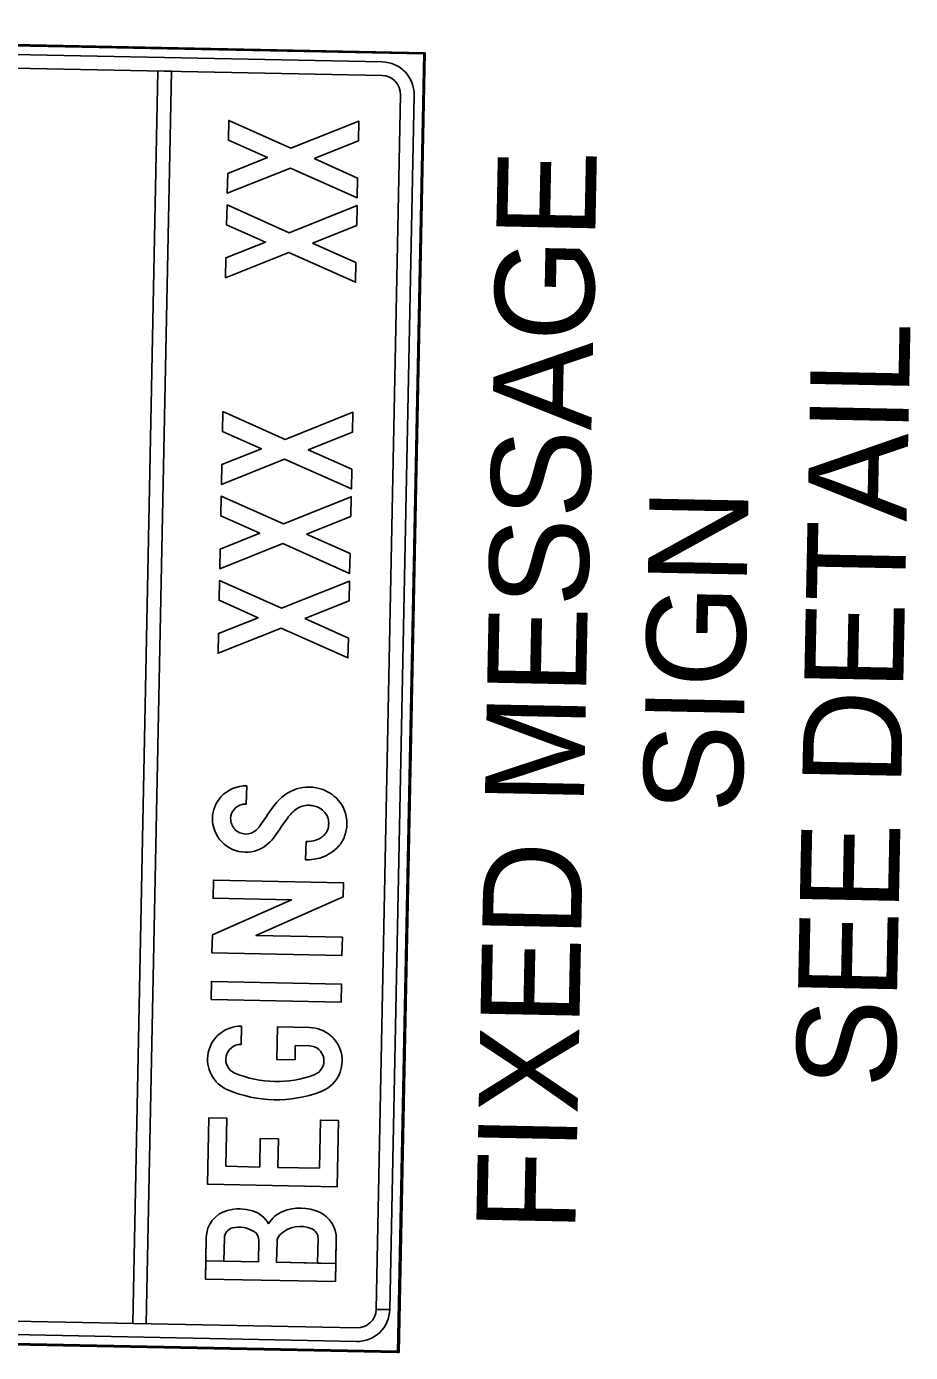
# Model space of a CAD drawing. Extents: x 331323 to 388339, y 121519 to 205315.
# Drawn here: x 366237 to 366773, y 139118 to 139921 of the extents above; entities that cross this region are included whole.
import ezdxf

# ---------------------------------------------------------------- set-up
doc = ezdxf.new("R2010")
doc.units = 0
doc.layers.add('P_MISC_TXT', color=7, linetype='Continuous')
doc.layers.add('P_SGN_Cell', color=7, linetype='Continuous')

msp = doc.modelspace()

# ---------------------------------------------------------------- linework, layer by layer
at = {"layer": 'P_MISC_TXT'}
for p, q in [((366478.7, 139904.99), (365691.28, 139920.84)), ((366478.7, 139904.99), (365691.28, 139920.84)), ((365692.08, 139920), (366477.86, 139904.19)), ((366452.74, 139899.36), (365716.99, 139914.17)), ((365716.82, 139905.96), (366452.58, 139891.16)), ((366462.86, 139117.57), (366478.7, 139904.99)), ((366462.86, 139117.57), (366478.7, 139904.99)), ((366477.86, 139904.19), (366462.03, 139117.59)), ((366316.85, 139893.89), (366301.58, 139135.17)), ((366316.85, 139893.89), (366301.58, 139135.17)), ((366316.85, 139893.89), (366301.58, 139135.17)), ((366309.79, 139135.01), (366325.05, 139893.73)), ((366309.79, 139135.01), (366325.05, 139893.73)), ((366309.79, 139135.01), (366325.05, 139893.73)), ((366325.05, 139893.73), (366316.85, 139893.89)), ((366325.05, 139893.73), (366316.85, 139893.89)), ((366325.05, 139893.73), (366316.85, 139893.89)), ((366463.83, 139879.45), (366449.03, 139143.77)), ((366457.23, 139143.61), (366472.03, 139879.28)), ((366367.18, 139304.19), (366367.4, 139315.21)), ((366367.18, 139304.19), (366367.4, 139315.21)), ((366367.18, 139304.19), (366367.4, 139315.21)), ((366400.05, 139303.52), (366408.51, 139303.35)), ((366400.05, 139303.52), (366408.51, 139303.35)), ((366400.05, 139303.52), (366408.51, 139303.35)), ((366437.31, 139132.44), (365701.56, 139147.25)), ((366457.22, 139143.53), (366449.02, 139143.69)), ((366449.03, 139143.77), (366457.23, 139143.61)), ((365675.44, 139133.42), (366462.86, 139117.57)), ((365675.44, 139133.42), (366462.03, 139117.59)), ((366462.04, 139118.41), (365676.27, 139134.22)), ((365701.39, 139139.05), (366437.15, 139124.24)), ((366301.58, 139135.17), (366309.79, 139135.01)), ((366301.58, 139135.17), (366309.79, 139135.01)), ((366301.58, 139135.17), (366309.79, 139135.01)), ((366462.03, 139117.59), (366462.04, 139118.41)), ((366462.03, 139117.59), (366462.86, 139117.57))]:
    msp.add_line(p, q, dxfattribs=at)
for points in [[(366411.41, 139840.82), (366438.25, 139851.54), (366438.49, 139863.51), (366397.38, 139847.09), (366359.74, 139863.91), (366359.5, 139851.94), (366383.11, 139841.39), (366359.09, 139831.79), (366358.85, 139819.82), (366397.14, 139835.12), (366437.55, 139817.06), (366437.79, 139829.03)], [(366411.41, 139840.82), (366438.25, 139851.54), (366438.49, 139863.51), (366397.38, 139847.09), (366359.74, 139863.91), (366359.5, 139851.94), (366383.11, 139841.39), (366359.09, 139831.79), (366358.85, 139819.82), (366397.14, 139835.12), (366437.55, 139817.06), (366437.79, 139829.03)], [(366411.41, 139840.82), (366438.25, 139851.54), (366438.49, 139863.51), (366397.38, 139847.09), (366359.74, 139863.91), (366359.5, 139851.94), (366383.11, 139841.39), (366359.09, 139831.79), (366358.85, 139819.82), (366397.14, 139835.12), (366437.55, 139817.06), (366437.79, 139829.03)], [(366410.38, 139789.65), (366437.22, 139800.37), (366437.46, 139812.34), (366396.35, 139795.92), (366358.71, 139812.74), (366358.47, 139800.77), (366382.08, 139790.22), (366358.06, 139780.62), (366357.82, 139768.65), (366396.11, 139783.95), (366436.52, 139765.89), (366436.76, 139777.85)], [(366410.38, 139789.65), (366437.22, 139800.37), (366437.46, 139812.34), (366396.35, 139795.92), (366358.71, 139812.74), (366358.47, 139800.77), (366382.08, 139790.22), (366358.06, 139780.62), (366357.82, 139768.65), (366396.11, 139783.95), (366436.52, 139765.89), (366436.76, 139777.85)], [(366410.38, 139789.65), (366437.22, 139800.37), (366437.46, 139812.34), (366396.35, 139795.92), (366358.71, 139812.74), (366358.47, 139800.77), (366382.08, 139790.22), (366358.06, 139780.62), (366357.82, 139768.65), (366396.11, 139783.95), (366436.52, 139765.89), (366436.76, 139777.85)], [(366407.86, 139664.47), (366434.7, 139675.19), (366434.94, 139687.16), (366393.83, 139670.74), (366356.19, 139687.56), (366355.95, 139675.6), (366379.57, 139665.04), (366355.54, 139655.45), (366355.3, 139643.48), (366393.59, 139658.77), (366434, 139640.71), (366434.24, 139652.68)], [(366407.86, 139664.47), (366434.7, 139675.19), (366434.94, 139687.16), (366393.83, 139670.74), (366356.19, 139687.56), (366355.95, 139675.6), (366379.57, 139665.04), (366355.54, 139655.45), (366355.3, 139643.48), (366393.59, 139658.77), (366434, 139640.71), (366434.24, 139652.68)], [(366407.86, 139664.47), (366434.7, 139675.19), (366434.94, 139687.16), (366393.83, 139670.74), (366356.19, 139687.56), (366355.95, 139675.6), (366379.57, 139665.04), (366355.54, 139655.45), (366355.3, 139643.48), (366393.59, 139658.77), (366434, 139640.71), (366434.24, 139652.68)], [(366406.83, 139613.3), (366433.67, 139624.02), (366433.91, 139635.99), (366392.8, 139619.57), (366355.16, 139636.39), (366354.92, 139624.43), (366378.54, 139613.87), (366354.51, 139604.27), (366354.27, 139592.31), (366392.56, 139607.6), (366432.97, 139589.54), (366433.21, 139601.51)], [(366406.83, 139613.3), (366433.67, 139624.02), (366433.91, 139635.99), (366392.8, 139619.57), (366355.16, 139636.39), (366354.92, 139624.43), (366378.54, 139613.87), (366354.51, 139604.27), (366354.27, 139592.31), (366392.56, 139607.6), (366432.97, 139589.54), (366433.21, 139601.51)], [(366406.83, 139613.3), (366433.67, 139624.02), (366433.91, 139635.99), (366392.8, 139619.57), (366355.16, 139636.39), (366354.92, 139624.43), (366378.54, 139613.87), (366354.51, 139604.27), (366354.27, 139592.31), (366392.56, 139607.6), (366432.97, 139589.54), (366433.21, 139601.51)], [(366405.8, 139562.13), (366432.64, 139572.85), (366432.88, 139584.82), (366391.77, 139568.4), (366354.13, 139585.22), (366353.89, 139573.25), (366377.51, 139562.7), (366353.48, 139553.1), (366353.24, 139541.13), (366391.53, 139556.43), (366431.94, 139538.37), (366432.18, 139550.34)], [(366405.8, 139562.13), (366432.64, 139572.85), (366432.88, 139584.82), (366391.77, 139568.4), (366354.13, 139585.22), (366353.89, 139573.25), (366377.51, 139562.7), (366353.48, 139553.1), (366353.24, 139541.13), (366391.53, 139556.43), (366431.94, 139538.37), (366432.18, 139550.34)], [(366405.8, 139562.13), (366432.64, 139572.85), (366432.88, 139584.82), (366391.77, 139568.4), (366354.13, 139585.22), (366353.89, 139573.25), (366377.51, 139562.7), (366353.48, 139553.1), (366353.24, 139541.13), (366391.53, 139556.43), (366431.94, 139538.37), (366432.18, 139550.34)], [(366429.03, 139393.51), (366429.2, 139402.17), (366350.48, 139403.76), (366350.26, 139392.74), (366397.83, 139391.78), (366349.81, 139370.56), (366349.59, 139359.67), (366428.32, 139358.09), (366428.54, 139369.11), (366376.18, 139370.16)], [(366429.03, 139393.51), (366429.2, 139402.17), (366350.48, 139403.76), (366350.26, 139392.74), (366397.83, 139391.78), (366349.81, 139370.56), (366349.59, 139359.67), (366428.32, 139358.09), (366428.54, 139369.11), (366376.18, 139370.16)], [(366429.03, 139393.51), (366429.2, 139402.17), (366350.48, 139403.76), (366350.26, 139392.74), (366397.83, 139391.78), (366349.81, 139370.56), (366349.59, 139359.67), (366428.32, 139358.09), (366428.54, 139369.11), (366376.18, 139370.16)], [(366349.02, 139331.33), (366349.24, 139342.35), (366427.97, 139340.77), (366427.75, 139329.75)], [(366349.02, 139331.33), (366349.24, 139342.35), (366427.97, 139340.77), (366427.75, 139329.75)], [(366349.02, 139331.33), (366349.24, 139342.35), (366427.97, 139340.77), (366427.75, 139329.75)], [(366414.7, 139229.2), (366389.5, 139229.7), (366389.85, 139246.95), (366378.83, 139247.17), (366378.48, 139229.93), (366358.01, 139230.34), (366358.6, 139259.47), (366347.58, 139259.69), (366346.77, 139219.54), (366425.5, 139217.95), (366426.3, 139258.1), (366415.28, 139258.33)], [(366414.7, 139229.2), (366389.5, 139229.7), (366389.85, 139246.95), (366378.83, 139247.17), (366378.48, 139229.93), (366358.01, 139230.34), (366358.6, 139259.47), (366347.58, 139259.69), (366346.77, 139219.54), (366425.5, 139217.95), (366426.3, 139258.1), (366415.28, 139258.33)], [(366414.7, 139229.2), (366389.5, 139229.7), (366389.85, 139246.95), (366378.83, 139247.17), (366378.48, 139229.93), (366358.01, 139230.34), (366358.6, 139259.47), (366347.58, 139259.69), (366346.77, 139219.54), (366425.5, 139217.95), (366426.3, 139258.1), (366415.28, 139258.33)]]:
    msp.add_lwpolyline(points, close=True, dxfattribs=at)
for points in [[(366370.37, 139449.82), (366370.59, 139460.85)], [(366370.37, 139449.82), (366370.59, 139460.85)], [(366370.37, 139449.82), (366370.59, 139460.85)], [(366406.53, 139427.04), (366406.3, 139416.02)], [(366406.53, 139427.04), (366406.3, 139416.02)], [(366406.53, 139427.04), (366406.3, 139416.02)], [(366408.73, 139314.38), (366389.25, 139314.77), (366388.85, 139295.09), (366399.87, 139294.86), (366400.05, 139303.52)], [(366408.73, 139314.38), (366389.25, 139314.77), (366388.85, 139295.09), (366399.87, 139294.86), (366400.05, 139303.52)], [(366408.73, 139314.38), (366389.25, 139314.77), (366388.85, 139295.09), (366399.87, 139294.86), (366400.05, 139303.52)], [(366346.12, 139187.26), (366345.61, 139162.07), (366424.34, 139160.48), (366424.86, 139186.36)], [(366388.99, 139184.66), (366388.74, 139172.23), (366424.56, 139171.51), (366424.34, 139160.48), (366345.61, 139162.07), (366345.84, 139173.09), (366377.72, 139172.45), (366377.98, 139185.32)], [(366388.99, 139184.66), (366388.74, 139172.23), (366424.56, 139171.51), (366424.34, 139160.48), (366345.61, 139162.07), (366345.84, 139173.09), (366377.72, 139172.45), (366377.98, 139185.32)], [(366357.14, 139187.04), (366356.86, 139172.87), (366345.84, 139173.09), (366346.12, 139187.26)], [(366357.14, 139187.04), (366356.86, 139172.87), (366345.84, 139173.09), (366346.12, 139187.26)], [(366377.98, 139185.32), (366377.72, 139172.45), (366356.86, 139172.87), (366357.14, 139187.04)], [(366413.84, 139186.59), (366413.54, 139171.73), (366388.74, 139172.23), (366388.99, 139184.66)], [(366424.86, 139186.36), (366424.56, 139171.51), (366413.54, 139171.73), (366413.84, 139186.59)], [(366424.86, 139186.36), (366424.56, 139171.51), (366413.54, 139171.73), (366413.84, 139186.59)]]:
    msp.add_lwpolyline(points, dxfattribs=at)
for centre, radius, start, end in [((366452.35, 139879.68), 19.69, 358.84724, 88.84724), ((366452.35, 139879.68), 11.48, 358.84724, 88.84724), ((366437.54, 139143.92), 19.69, 268.84724, 358.84724), ((366437.54, 139143.92), 11.48, 268.84724, 358.84724)]:
    msp.add_arc(centre, radius, start, end, dxfattribs=at)
for centre, major_axis, start_param, end_param in [((366370.18, 139440.26), (-20.58, 0.41), 4.712389, 5.561989), ((366370.18, 139440.26), (-20.58, 0.41), 4.712389, 5.561989), ((366370.18, 139440.26), (-20.58, 0.41), 4.712389, 5.561989), ((366414.03, 139428.15), (-33.9, 0.68), 5.373599, 5.679143), ((366414.03, 139428.15), (-33.9, 0.68), 5.373599, 5.679143), ((366414.03, 139428.15), (-33.9, 0.68), 5.373599, 5.679143), ((366408.09, 139436.1), (-23.98, 0.48), 4.712389, 5.373599), ((366408.09, 139436.1), (-23.98, 0.48), 4.712389, 5.373599), ((366408.09, 139436.1), (-23.98, 0.48), 4.712389, 5.373599), ((366408.05, 139433.86), (-26.22, 0.53), 4.552917, 4.712389), ((366408.05, 139433.86), (-26.22, 0.53), 4.552917, 4.712389), ((366408.05, 139433.86), (-26.22, 0.53), 4.552917, 4.712389), ((366408.55, 139436.65), (-23.38, 0.47), 3.967076, 4.552917), ((366408.55, 139436.65), (-23.38, 0.47), 3.967076, 4.552917), ((366408.55, 139436.65), (-23.38, 0.47), 3.967076, 4.552917), ((366369.45, 139440.93), (-19.59, 0.39), 5.561989, 6.283185), ((366369.45, 139440.93), (-19.59, 0.39), 5.561989, 6.283185), ((366369.45, 139440.93), (-19.59, 0.39), 5.561989, 6.283185), ((366369.45, 139440.93), (-8.57, 0.17), 5.561989, 6.283185), ((366369.45, 139440.93), (-8.57, 0.17), 5.561989, 6.283185), ((366369.45, 139440.93), (-8.57, 0.17), 5.561989, 6.283185), ((366370.18, 139440.26), (-9.56, 0.19), 4.712389, 5.561989), ((366370.18, 139440.26), (-9.56, 0.19), 4.712389, 5.561989), ((366370.18, 139440.26), (-9.56, 0.19), 4.712389, 5.561989), ((366762.58, 139177.12), (-463.35, 9.32), 5.679143, 5.709053), ((366762.58, 139177.12), (-463.35, 9.32), 5.679143, 5.709053), ((366762.58, 139177.12), (-463.35, 9.32), 5.679143, 5.709053), ((366408.09, 139436.1), (-12.96, 0.26), 4.712389, 5.373599), ((366408.09, 139436.1), (-12.96, 0.26), 4.712389, 5.373599), ((366408.09, 139436.1), (-12.96, 0.26), 4.712389, 5.373599), ((366408.05, 139433.86), (-15.19, 0.31), 4.552917, 4.712389), ((366408.05, 139433.86), (-15.19, 0.31), 4.552917, 4.712389), ((366408.05, 139433.86), (-15.19, 0.31), 4.552917, 4.712389), ((366408.55, 139436.65), (-12.36, 0.25), 3.967076, 4.552917), ((366408.55, 139436.65), (-12.36, 0.25), 3.967076, 4.552917), ((366408.55, 139436.65), (-12.36, 0.25), 3.967076, 4.552917), ((366410, 139438.16), (-21.3, 0.43), 3.141593, 3.967076), ((366410, 139438.16), (-21.3, 0.43), 3.141593, 3.967076), ((366410, 139438.16), (-21.3, 0.43), 3.141593, 3.967076), ((366370.14, 139440.92), (-20.28, 0.41), 6.283184, 7.853982), ((366370.14, 139440.92), (-20.28, 0.41), 6.283184, 7.853982), ((366370.14, 139440.92), (-20.28, 0.41), 6.283184, 7.853982), ((366370.14, 139440.92), (-9.26, 0.19), 6.283183, 7.853981), ((366370.14, 139440.92), (-9.26, 0.19), 6.283183, 7.853981), ((366370.14, 139440.92), (-9.26, 0.19), 6.283183, 7.853981), ((366762.58, 139177.12), (-452.33, 9.1), 5.679143, 5.709053), ((366762.58, 139177.12), (-452.33, 9.1), 5.679143, 5.709053), ((366762.58, 139177.12), (-452.33, 9.1), 5.679143, 5.709053), ((366414.03, 139428.15), (-22.88, 0.46), 5.373599, 5.679143), ((366414.03, 139428.15), (-22.88, 0.46), 5.373599, 5.679143), ((366414.03, 139428.15), (-22.88, 0.46), 5.373599, 5.679143), ((366410, 139438.16), (-10.28, 0.21), 3.141593, 3.967076), ((366410, 139438.16), (-10.28, 0.21), 3.141593, 3.967076), ((366410, 139438.16), (-10.28, 0.21), 3.141593, 3.967076), ((366370.14, 139440.96), (-9.3, 0.19), 1.570796, 2.321595), ((366370.14, 139440.96), (-9.3, 0.19), 1.570796, 2.321595), ((366370.14, 139440.96), (-9.3, 0.19), 1.570796, 2.321595), ((366367.08, 139444.37), (-13.88, 0.28), 2.321595, 2.56746), ((366367.08, 139444.37), (-13.88, 0.28), 2.321595, 2.56746), ((366367.08, 139444.37), (-13.88, 0.28), 2.321595, 2.56746), ((366408.54, 139440.05), (-12.74, 0.26), 1.909925, 2.431476), ((366408.54, 139440.05), (-12.74, 0.26), 1.909925, 2.431476), ((366408.54, 139440.05), (-12.74, 0.26), 1.909925, 2.431476), ((366412.23, 139436.74), (-7.79, 0.16), 2.431476, 2.811358), ((366412.23, 139436.74), (-7.79, 0.16), 2.431476, 2.811358), ((366412.23, 139436.74), (-7.79, 0.16), 2.431476, 2.811358), ((366408.27, 139438.19), (-12.01, 0.24), 2.811358, 3.141593), ((366408.27, 139438.19), (-12.01, 0.24), 2.811358, 3.141593), ((366408.27, 139438.19), (-12.01, 0.24), 2.811358, 3.141593), ((366408.27, 139438.19), (-23.03, 0.46), 2.811358, 3.141593), ((366408.27, 139438.19), (-23.03, 0.46), 2.811358, 3.141593), ((366408.27, 139438.19), (-23.03, 0.46), 2.811358, 3.141593), ((366370.14, 139440.96), (-20.32, 0.41), 1.570796, 2.321595), ((366370.14, 139440.96), (-20.32, 0.41), 1.570796, 2.321595), ((366370.14, 139440.96), (-20.32, 0.41), 1.570796, 2.321595), ((366367.08, 139444.37), (-24.9, 0.5), 2.321595, 2.56746), ((366367.08, 139444.37), (-24.9, 0.5), 2.321595, 2.56746), ((366367.08, 139444.37), (-24.9, 0.5), 2.321595, 2.56746), ((366406.89, 139445.06), (-18.01, 0.36), 1.570816, 1.909918), ((366406.89, 139445.06), (-18.01, 0.36), 1.570816, 1.909918), ((366406.89, 139445.06), (-18.01, 0.36), 1.570816, 1.909918), ((366408.54, 139440.05), (-23.76, 0.48), 1.909925, 2.431476), ((366408.54, 139440.05), (-23.76, 0.48), 1.909925, 2.431476), ((366408.54, 139440.05), (-23.76, 0.48), 1.909925, 2.431476), ((366412.23, 139436.74), (-18.81, 0.38), 2.431476, 2.811358), ((366412.23, 139436.74), (-18.81, 0.38), 2.431476, 2.811358), ((366412.23, 139436.74), (-18.81, 0.38), 2.431476, 2.811358), ((366406.89, 139445.06), (-29.04, 0.58), 1.570808, 1.909921), ((366406.89, 139445.06), (-29.04, 0.58), 1.570808, 1.909921), ((366406.89, 139445.06), (-29.04, 0.58), 1.570808, 1.909921), ((366367, 139295.13), (-20.08, 0.4), 4.712389, 7.477539), ((366367, 139295.13), (-20.08, 0.4), 4.712389, 7.477539), ((366367, 139295.13), (-20.08, 0.4), 4.712389, 7.477539), ((366408.33, 139294.3), (-20.08, 0.4), 1.947239, 4.712389), ((366408.33, 139294.3), (-20.08, 0.4), 1.947239, 4.712389), ((366408.33, 139294.3), (-20.08, 0.4), 1.947239, 4.712389), ((366367, 139295.13), (-9.05, 0.18), 4.712389, 7.477539), ((366367, 139295.13), (-9.05, 0.18), 4.712389, 7.477539), ((366367, 139295.13), (-9.05, 0.18), 4.712389, 7.477539), ((366408.33, 139294.3), (-9.05, 0.18), 1.947239, 4.712389), ((366408.33, 139294.3), (-9.05, 0.18), 1.947239, 4.712389), ((366408.33, 139294.3), (-9.05, 0.18), 1.947239, 4.712389), ((366388.71, 139347), (-65.27, 1.31), 1.194353, 1.947239), ((366388.71, 139347), (-65.27, 1.31), 1.194353, 1.947239), ((366388.71, 139347), (-65.27, 1.31), 1.194353, 1.947239), ((366388.71, 139347), (-76.29, 1.54), 1.194353, 1.947239), ((366388.71, 139347), (-76.29, 1.54), 1.194353, 1.947239), ((366388.71, 139347), (-76.29, 1.54), 1.194353, 1.947239), ((366403.01, 139176.67), (-28.34, 0.57), 4.308652, 5.116125), ((366403.01, 139176.67), (-28.34, 0.57), 4.308653, 5.116125), ((366403.01, 139176.67), (-28.34, 0.57), 4.308653, 5.116125), ((366363.44, 139186.91), (-17.32, 0.35), 4.996183, 6.283185), ((366363.44, 139186.91), (-17.32, 0.35), 4.996183, 6.283185), ((366363.44, 139186.91), (-17.32, 0.35), 4.996183, 6.283185), ((366366.01, 139177.41), (-27.16, 0.55), 4.428595, 4.996183), ((366366.01, 139177.41), (-27.16, 0.55), 4.428595, 4.996183), ((366366.01, 139177.41), (-27.16, 0.55), 4.428595, 4.996183), ((366368.95, 139186.8), (-17.32, 0.35), 3.692503, 4.428595), ((366368.95, 139186.8), (-17.32, 0.35), 3.692503, 4.428595), ((366368.95, 139186.8), (-17.32, 0.35), 3.692503, 4.428595), ((366398.88, 139186.89), (-17.32, 0.35), 5.116125, 5.778288), ((366398.88, 139186.89), (-17.32, 0.35), 5.116125, 5.778288), ((366398.88, 139186.89), (-17.32, 0.35), 5.116125, 5.778288), ((366407.54, 139186.71), (-17.32, 0.35), 3.141593, 4.308652), ((366407.54, 139186.71), (-17.32, 0.35), 3.141593, 4.308652), ((366407.54, 139186.71), (-17.32, 0.35), 3.141593, 4.308652), ((366363.44, 139186.91), (-6.3, 0.13), 4.996183, 6.283185), ((366363.44, 139186.91), (-6.3, 0.13), 4.996183, 6.283185), ((366363.44, 139186.91), (-6.3, 0.13), 4.996183, 6.283185), ((366366.01, 139177.41), (-16.14, 0.32), 4.118003, 4.996183), ((366366.01, 139177.41), (-16.14, 0.32), 4.118003, 4.996183), ((366366.01, 139177.41), (-16.14, 0.32), 4.118003, 4.996183), ((366371.68, 139185.45), (-6.3, 0.13), 3.141593, 4.118003), ((366371.68, 139185.45), (-6.3, 0.13), 3.141593, 4.118003), ((366371.68, 139185.45), (-6.3, 0.13), 3.141593, 4.118003), ((366403.01, 139176.67), (-17.32, 0.35), 4.308652, 5.507992), ((366403.01, 139176.67), (-17.32, 0.35), 4.308652, 5.507992), ((366403.01, 139176.67), (-17.32, 0.35), 4.308652, 5.507992), ((366407.54, 139186.71), (-6.3, 0.13), 3.141593, 4.308652), ((366407.54, 139186.71), (-6.3, 0.13), 3.141593, 4.308652), ((366407.54, 139186.71), (-6.3, 0.13), 3.141593, 4.308652), ((366395.29, 139184.54), (-6.3, 0.13), 5.507992, 6.283185), ((366395.29, 139184.54), (-6.3, 0.13), 5.507992, 6.283185), ((366395.29, 139184.54), (-6.3, 0.13), 5.507992, 6.283185)]:
    msp.add_ellipse(centre, major_axis=major_axis, ratio=0.999993, start_param=start_param, end_param=end_param, dxfattribs=at)

# ---------------------------------------------------------------- texts
at = {"layer": 'P_SGN_Cell'}
for s, p in [('FIXED MESSAGE', (366569.57, 139190.25)), ('SEE DETAIL', (366763.36, 139277.54)), ('SIGN', (366670.7, 139444.07))]:
    msp.add_text(s, height=60, rotation=88.84622, dxfattribs=at).set_placement(p)

doc.saveas('drawing.dxf')
